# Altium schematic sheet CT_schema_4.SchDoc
size 556 x 419 mm
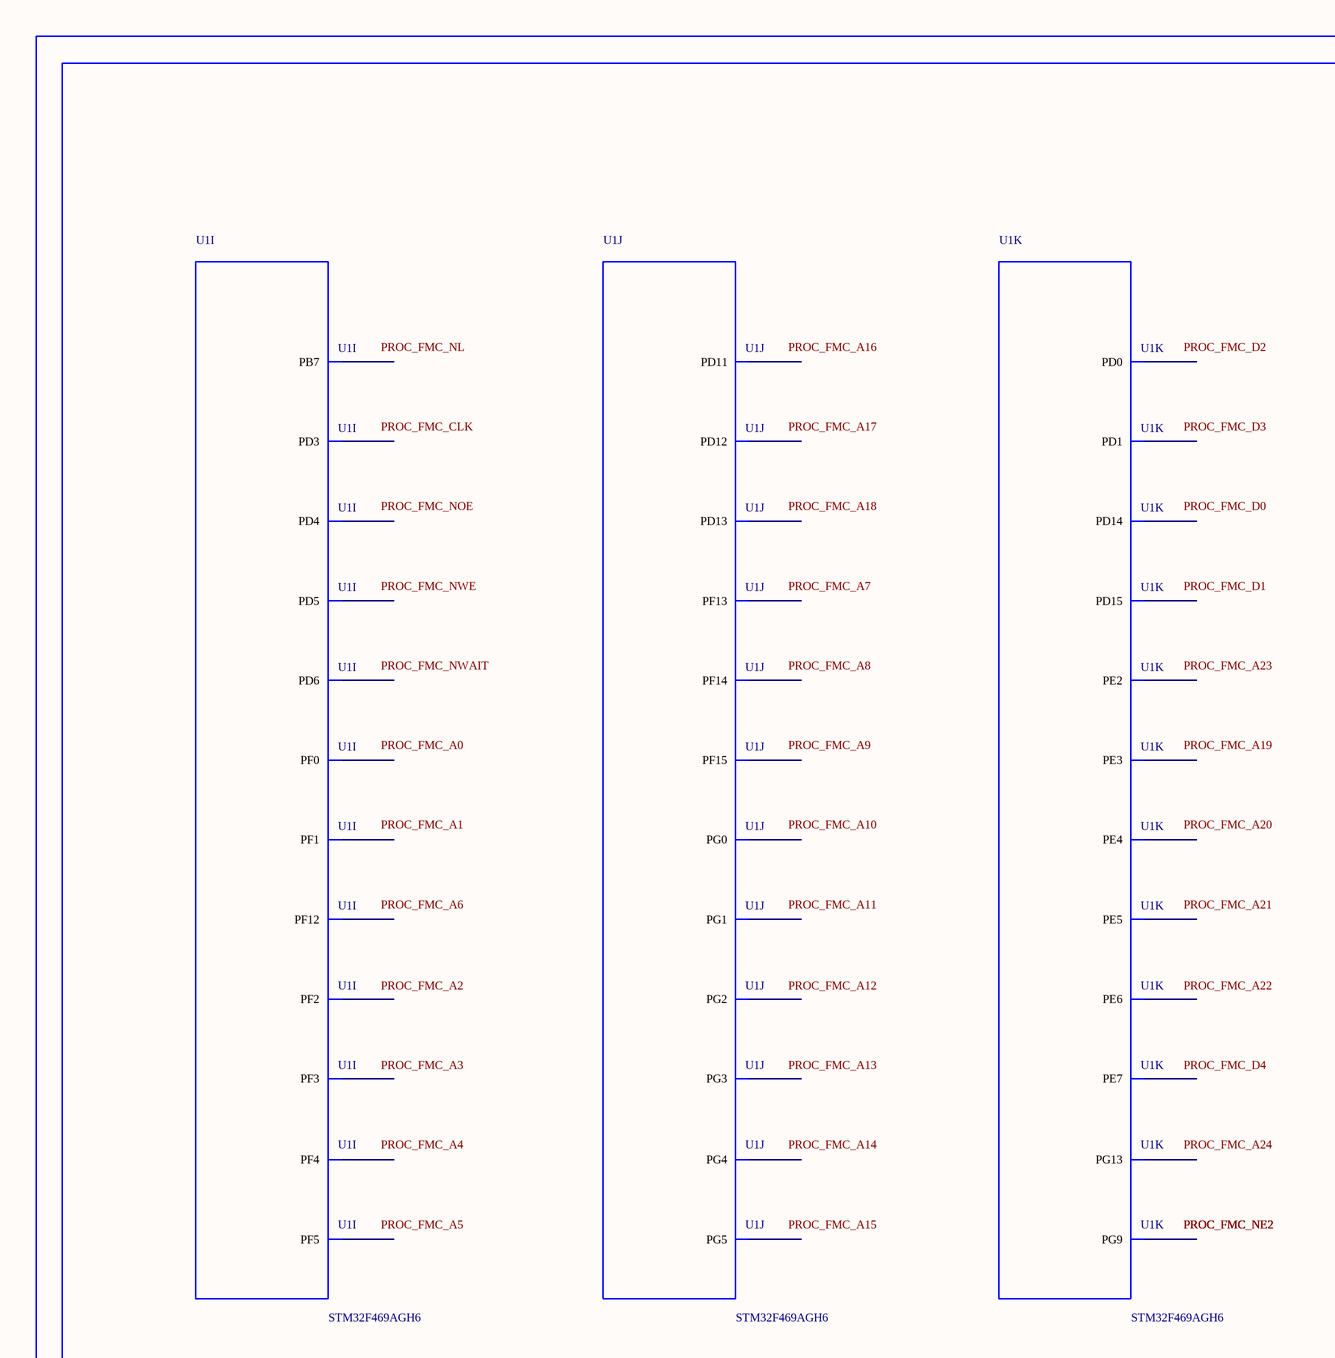
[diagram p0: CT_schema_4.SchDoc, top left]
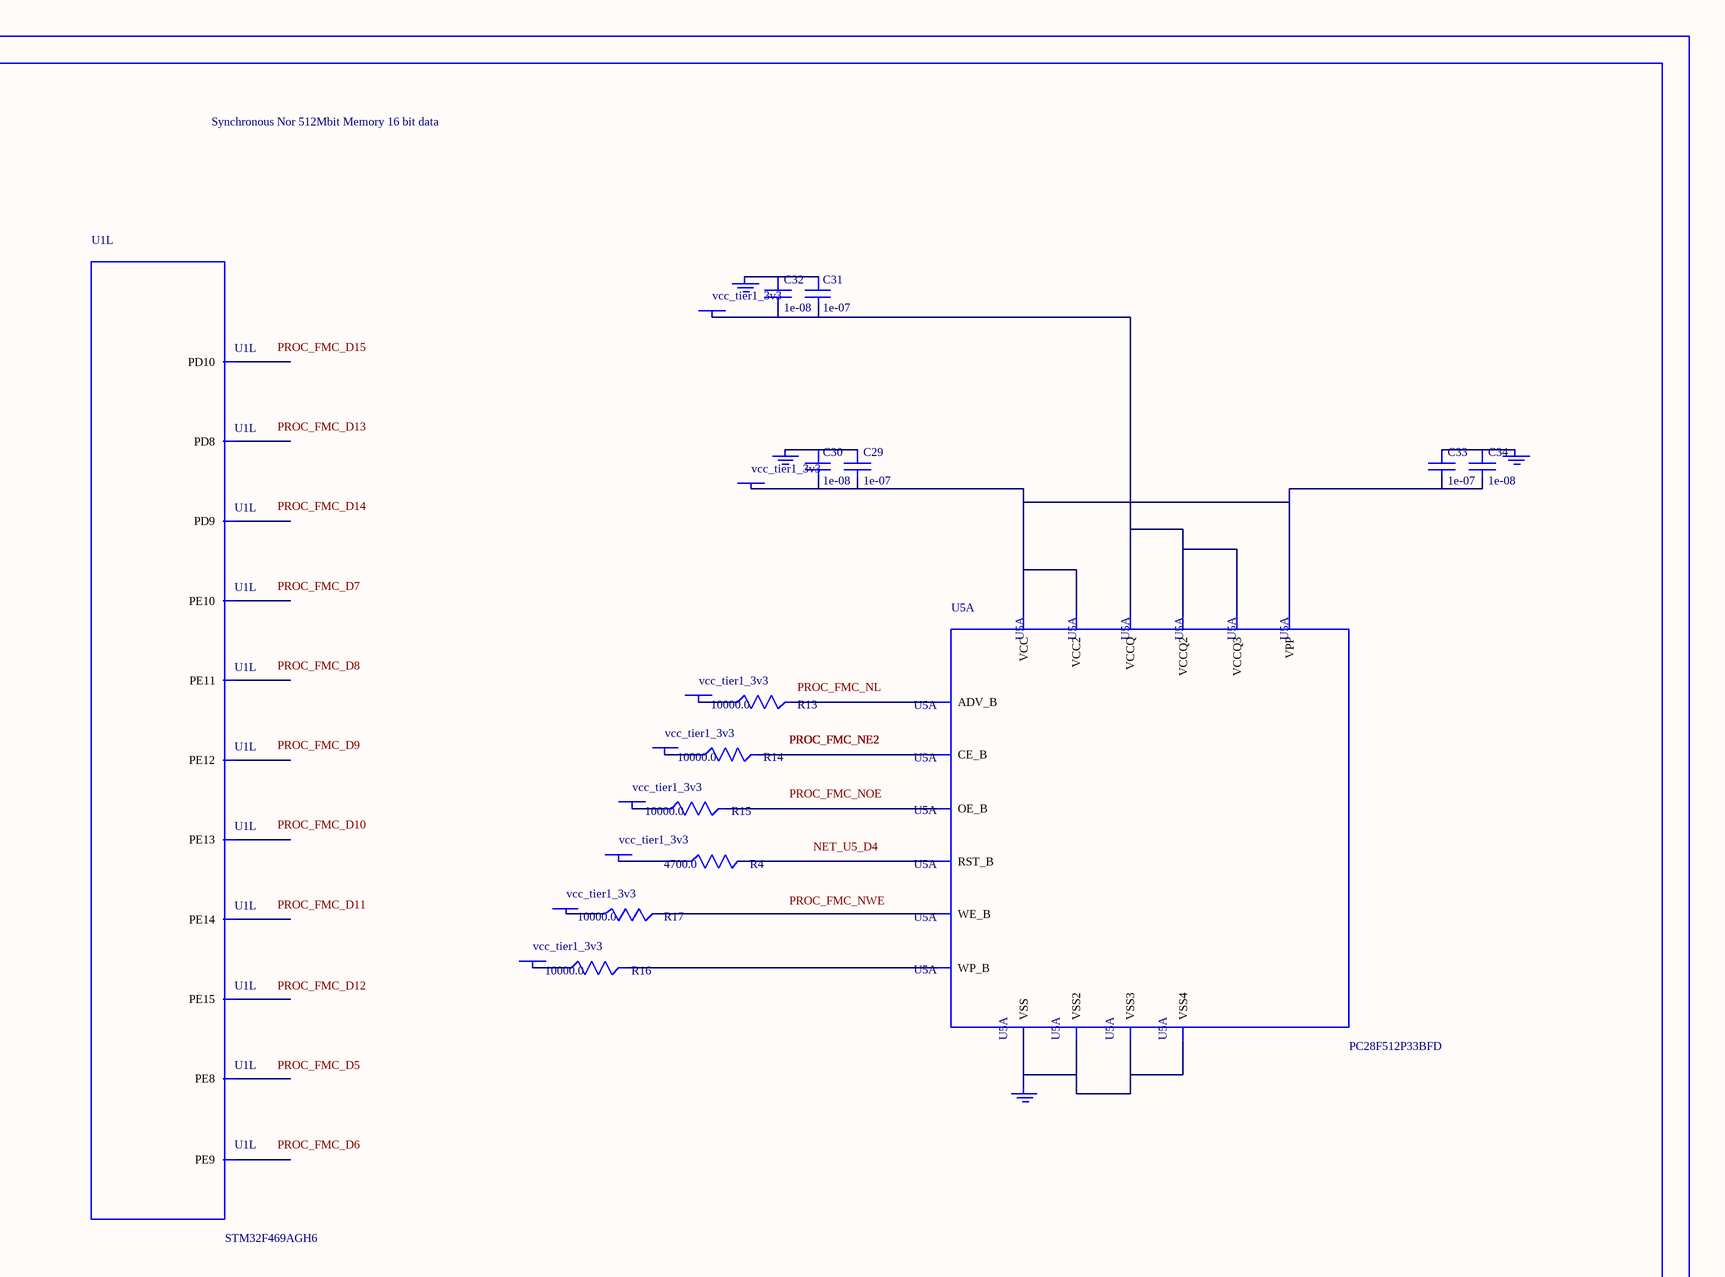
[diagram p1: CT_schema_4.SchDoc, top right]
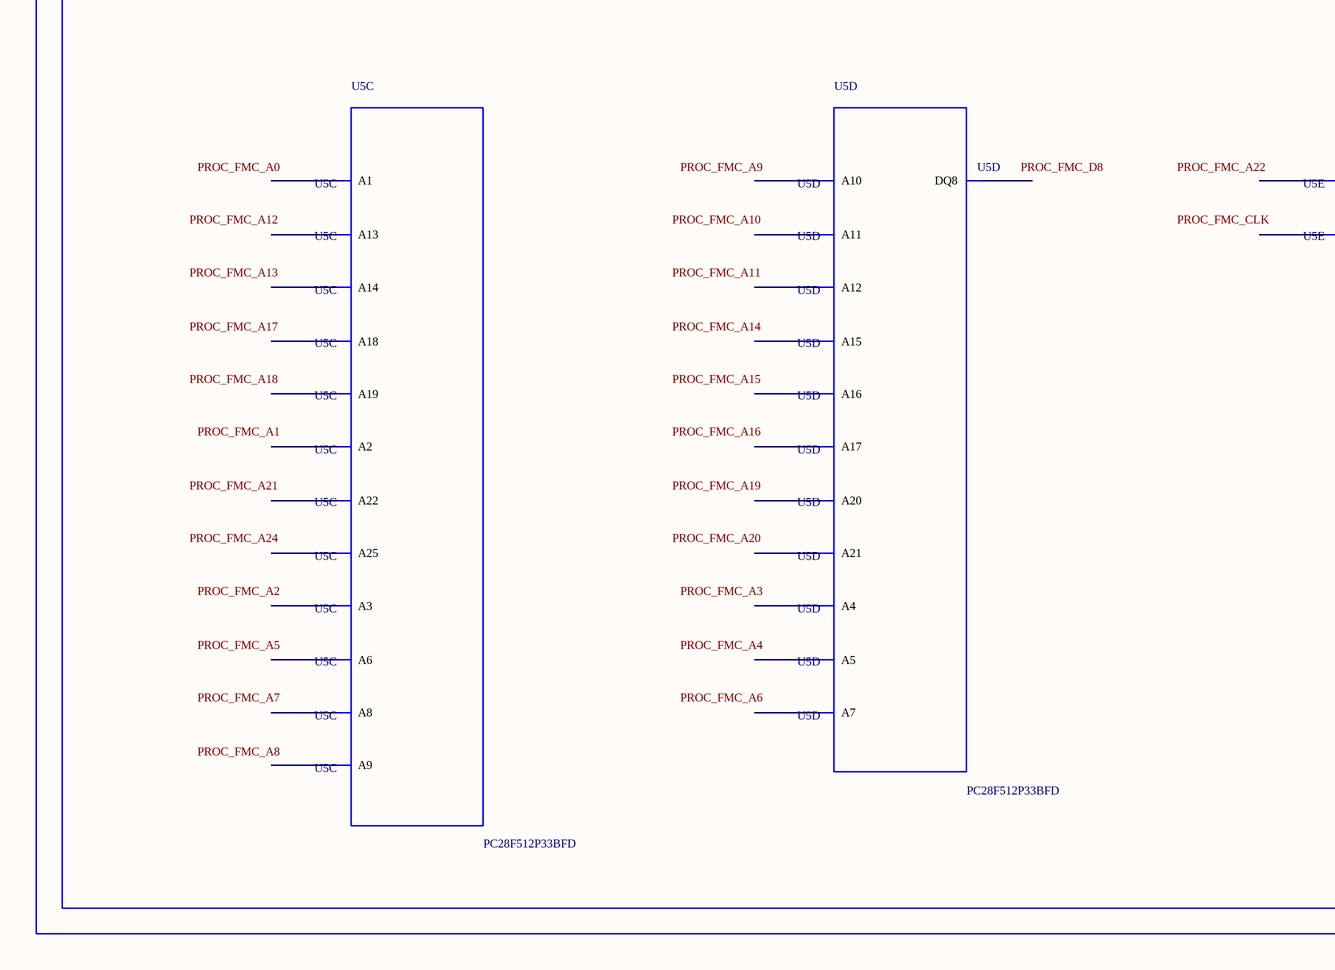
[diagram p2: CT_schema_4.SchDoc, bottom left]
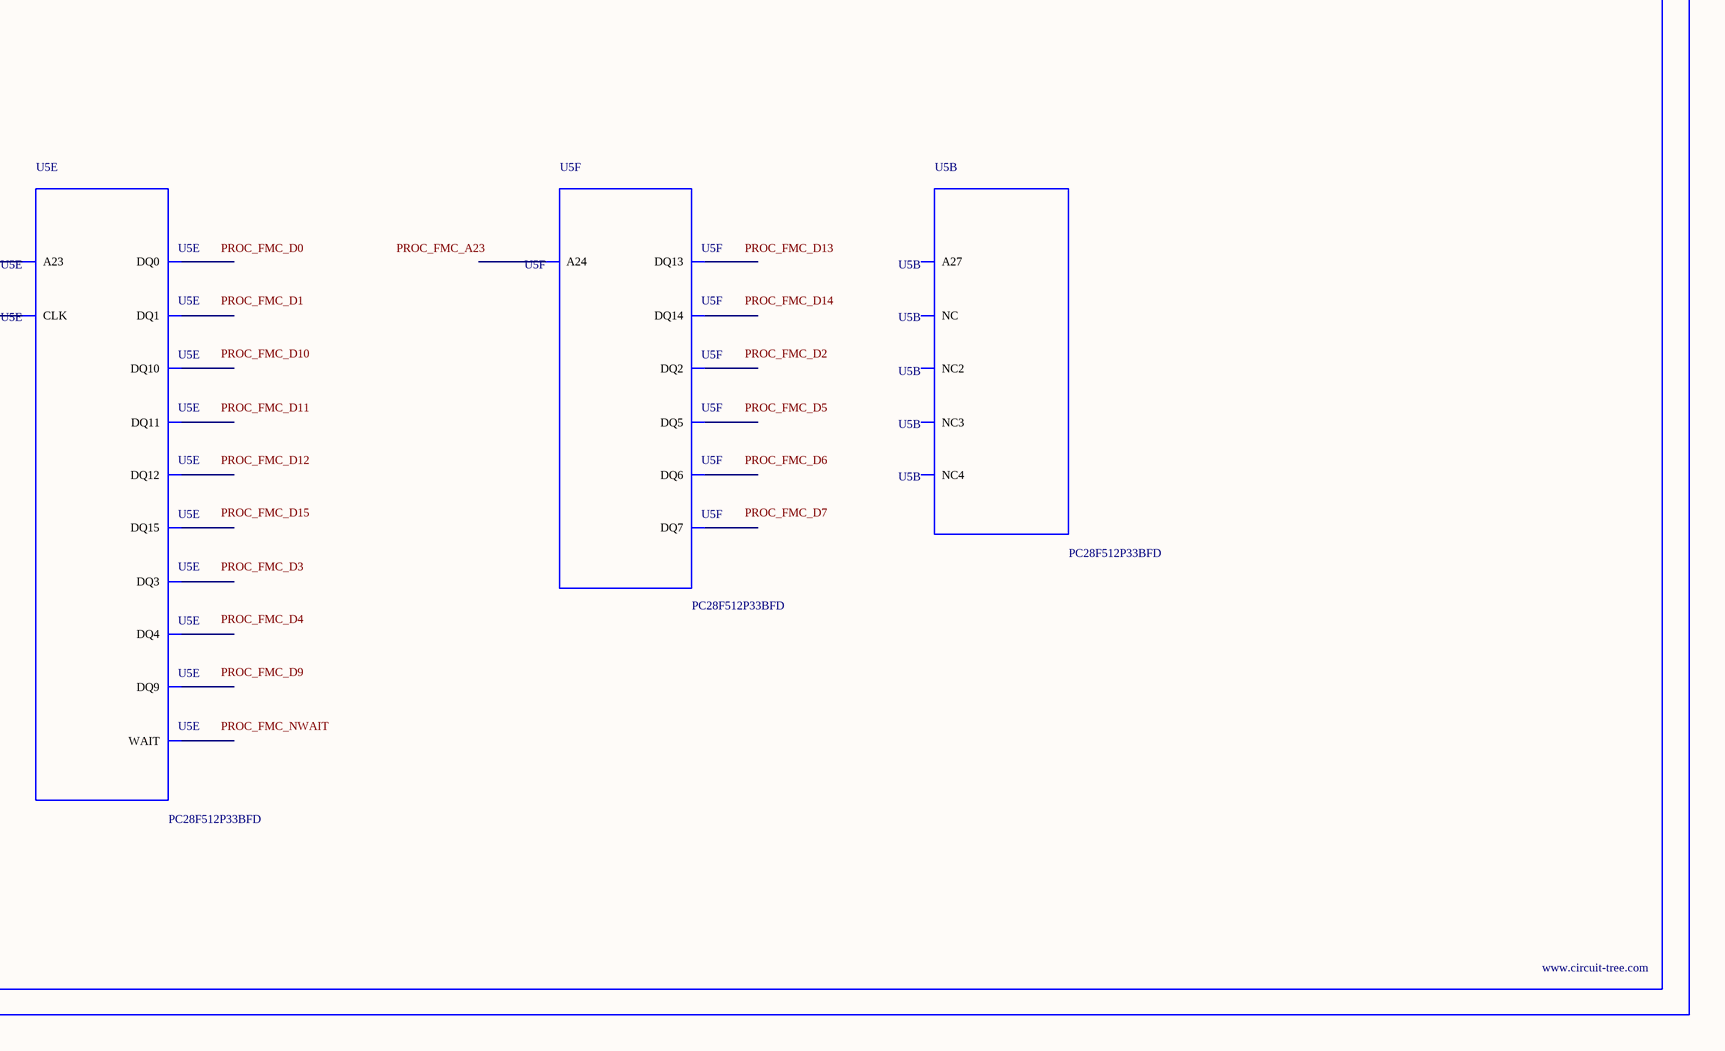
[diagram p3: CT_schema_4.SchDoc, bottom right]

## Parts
BORDER3  (no value)
C29  1e-07  [C0402]
C30  1e-08  [C0402]
C31  1e-07  [C0402]
C32  1e-08  [C0402]
C33  1e-07  [C0402]
C34  1e-08  [C0402]
GND_INSTANCE_3_0  (no value)
GND_INSTANCE_3_1  (no value)
GND_INSTANCE_3_2  (no value)
GND_INSTANCE_3_3  (no value)
POWER_INSTANCE_3_0  vcc_tier1_3v3
POWER_INSTANCE_3_1  vcc_tier1_3v3
POWER_INSTANCE_3_2  vcc_tier1_3v3
POWER_INSTANCE_3_3  vcc_tier1_3v3
POWER_INSTANCE_3_4  vcc_tier1_3v3
POWER_INSTANCE_3_5  vcc_tier1_3v3
POWER_INSTANCE_3_6  vcc_tier1_3v3
POWER_INSTANCE_3_7  vcc_tier1_3v3
R4  4700.0  [R0603]
R13  10000.0  [R0603]
R14  10000.0  [R0603]
R15  10000.0  [R0603]
R16  10000.0  [R0603]
R17  10000.0  [R0603]
U1  STM32F469AGH6  [UFBGA169]  (parts I,J,K,L of 14)
U5  PC28F512P33BFD  [PC28F512P33BFD]  (parts A,B,C,D,E,F of 6)

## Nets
NetC29_1: C29.1 C30.1 GND_INSTANCE_3_0.0(GND)
NetC29_2: C29.2 C30.2 C33.2 C34.2 POWER_INSTANCE_3_0.0(PWR) U5.A4(VPP) U5.A6(VCC) U5.H3(VCC2)
NetC31_1: C31.1 C32.1 GND_INSTANCE_3_1.0(GND)
NetC31_2: C31.2 C32.2 POWER_INSTANCE_3_1.0(PWR) U5.D5(VCCQ) U5.D6(VCCQ2) U5.G4(VCCQ3)
NetC33_1: C33.1 C34.1 GND_INSTANCE_3_2.0(GND)
NetGND_INSTANCE_3_3_0: GND_INSTANCE_3_3.0(GND) U5.B2(VSS) U5.H2(VSS2) U5.H4(VSS3) U5.H6(VSS4)
NetPOWER_INSTANCE_3_2_0: POWER_INSTANCE_3_2.0(PWR) R13.1
NetPOWER_INSTANCE_3_3_0: POWER_INSTANCE_3_3.0(PWR) R14.1
NetPOWER_INSTANCE_3_4_0: POWER_INSTANCE_3_4.0(PWR) R15.1
NetPOWER_INSTANCE_3_5_0: POWER_INSTANCE_3_5.0(PWR) R16.1
NetPOWER_INSTANCE_3_6_0: POWER_INSTANCE_3_6.0(PWR) R17.1
NetPOWER_INSTANCE_3_7_0: POWER_INSTANCE_3_7.0(PWR) R4.1
NetR4_2: R4.2 U5.D4(RST_B)
NetR13_2: R13.2 U5.F6(ADV_B)
NetR14_2: R14.2 U5.B4(CE_B)
NetR15_2: R15.2 U5.F8(OE_B)
NetR16_2: R16.2 U5.C6(WP_B)
NetR17_2: R17.2 U5.G8(WE_B)

Not connected (* = marked no-connect by the designer): U1 A6(PG13) B2(PE2) B4(PB7) B7(PD5) C1(PE3) C2(PE4) C6(PD4) C7(PD1) C8(PD3) C9(PD0) D1(PE5) D2(PE6) D7(PD6) E6(PG9) E12(PG5) E13(PG4) F3(PF0) F12(PG3) F13(PG2) G3(PF1) G5(PF2) G6(PE8) H3(PF5) H4(PF3) H5(PF14) H6(PE9) H7(PE10) J8(PE13) K7(PE11) K8(PE14) L4(PF4) L7(PE12) L8(PE15) L10(PD8) L11(PD10) L12(PD14) L13(PD15) M4(PF13) M6(PF15) M7(PG1) M10(PD9) M11(PD11) M12(PD13) M13(PD12) N5(PF12) N6(PG0) N7(PE7); U5 A1 A2(A6) A3(A8) A5(A13) A7(A18) A8(A22) B1(A2) B3(A9) B5(A14) B6(A25) B7(A19) B8(NC) C1(A3) C2(A7) C3(A10) C4(A12) C5(A15) C7(A20) C8(A21) D1(A4) D2(A5) D3(A11) D7(A16) D8(A17) E1(DQ8) E2(DQ1) E3(DQ9) E4(DQ3) E5(DQ4) E6(CLK) E7(DQ15) E8(NC2) F1(NC3) F2(DQ0) F3(DQ10) F4(DQ11) F5(DQ12) F7(WAIT) G1(A23) G2(NC4) G3(DQ2) G5(DQ5) G6(DQ6) G7(DQ14) H1(A27) H5(DQ13) H7(DQ7) H8(A24)

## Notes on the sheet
- Labels drawn without touching a wire or pin: NET_U5_D4, PROC_FMC_A0, PROC_FMC_A1, PROC_FMC_A2, PROC_FMC_A3, PROC_FMC_A4, PROC_FMC_A5, PROC_FMC_A6, PROC_FMC_A7, PROC_FMC_A8, PROC_FMC_A9, PROC_FMC_A10, PROC_FMC_A11, PROC_FMC_A12, PROC_FMC_A13, PROC_FMC_A14, PROC_FMC_A15, PROC_FMC_A16, PROC_FMC_A17, PROC_FMC_A18, PROC_FMC_A19, PROC_FMC_A20, PROC_FMC_A21, PROC_FMC_A22, PROC_FMC_A23, PROC_FMC_A24, PROC_FMC_CLK, PROC_FMC_D0, PROC_FMC_D1, PROC_FMC_D2, PROC_FMC_D3, PROC_FMC_D4, PROC_FMC_D5, PROC_FMC_D6, PROC_FMC_D7, PROC_FMC_D8, PROC_FMC_D9, PROC_FMC_D10, PROC_FMC_D11, PROC_FMC_D12, PROC_FMC_D13, PROC_FMC_D14, PROC_FMC_D15, PROC_FMC_NL, PROC_FMC_NOE, PROC_FMC_NWAIT, PROC_FMC_NWE

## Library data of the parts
BORDER3 = BORDER_PAGE3
C29 C31 C33 = C0402C104K3RACTU
C30 C32 C34 = C0402C103K3RAC
GND_INSTANCE_3_0-GND_INSTANCE_3_3 = GND
POWER_INSTANCE_3_0-POWER_INSTANCE_3_7 = PWR
R4 = RC0603JR-074K7L
R13-R17 = RC0603JR-0710KL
